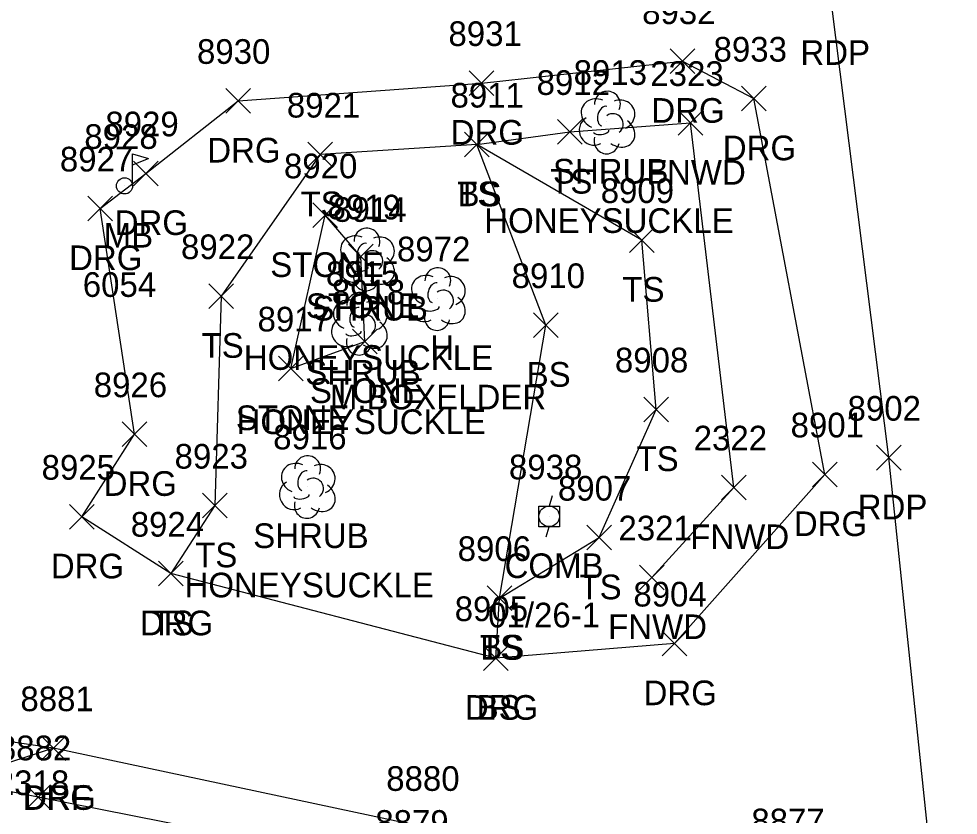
# Model space of a CAD drawing. Extents: x 1439173 to 1457902, y 641926 to 659889.
# Drawn here: x 1448240 to 1448316.2, y 646072.4 to 646137 of the extents above; entities that cross this region are included whole.
import ezdxf

# ---------------------------------------------------------------- set-up
doc = ezdxf.new("R2010")
doc.units = 0
for name, color, linetype in [('L_A', 7, 'Continuous'), ('L_C', 7, 'Continuous'), ('L_I', 7, 'Continuous'), ('L_TIC', 7, 'Continuous'), ('LASF', 7, 'Continuous'), ('LELB', 7, 'Continuous'), ('LFNC', 7, 'Continuous'), ('LMB', 7, 'Continuous'), ('LSH', 7, 'Continuous'), ('LTD', 7, 'Continuous'), ('P_A', 7, 'Continuous'), ('P_I', 7, 'Continuous'), ('P_TIC', 7, 'Continuous'), ('PET', 7, 'Continuous'), ('R_A', 7, 'Continuous'), ('R_I', 7, 'Continuous'), ('R_TIC', 7, 'Continuous'), ('RDF', 7, 'Continuous'), ('RDG', 7, 'Continuous'), ('U_A', 7, 'Continuous'), ('U_C', 7, 'Continuous'), ('U_I', 7, 'Continuous'), ('UP', 7, 'Continuous')]:
    doc.layers.add(name, color=color, linetype=linetype)

msp = doc.modelspace()

# ---------------------------------------------------------------- linework, layer by layer
at = {"layer": 'L_TIC'}
for points in [[(1448293.487, 646127.507), (1448295.487, 646129.507)], [(1448295.487, 646127.507), (1448293.487, 646129.507)], [(1448283.703, 646126.78), (1448285.703, 646128.78)], [(1448285.703, 646126.78), (1448283.703, 646128.78)], [(1448276.159, 646125.756), (1448278.159, 646127.756)], [(1448278.159, 646125.756), (1448276.159, 646127.756)], [(1448276.159, 646125.756), (1448278.159, 646127.756)], [(1448278.159, 646125.756), (1448276.159, 646127.756)], [(1448276.159, 646125.756), (1448278.159, 646127.756)], [(1448278.159, 646125.756), (1448276.159, 646127.756)], [(1448263.455, 646124.945), (1448265.455, 646126.945)], [(1448265.455, 646124.945), (1448263.455, 646126.945)], [(1448263.874, 646120.02), (1448265.874, 646122.02)], [(1448265.874, 646120.02), (1448263.874, 646122.02)], [(1448263.874, 646120.02), (1448265.874, 646122.02)], [(1448265.874, 646120.02), (1448263.874, 646122.02)], [(1448289.554, 646118.016), (1448291.554, 646120.016)], [(1448291.554, 646118.016), (1448289.554, 646120.016)], [(1448266.759, 646116.687), (1448268.759, 646118.687)], [(1448268.759, 646116.687), (1448266.759, 646118.687)], [(1448255.439, 646113.467), (1448257.439, 646115.467)], [(1448257.439, 646113.467), (1448255.439, 646115.467)], [(1448281.765, 646111.121), (1448283.765, 646113.121)], [(1448283.765, 646111.121), (1448281.765, 646113.121)], [(1448267.093, 646109.801), (1448269.093, 646111.801)], [(1448269.093, 646109.801), (1448267.093, 646111.801)], [(1448261.081, 646107.602), (1448263.081, 646109.602)], [(1448263.081, 646107.602), (1448261.081, 646109.602)], [(1448261.081, 646107.602), (1448263.081, 646109.602)], [(1448263.081, 646107.602), (1448261.081, 646109.602)], [(1448290.699, 646104.283), (1448292.699, 646106.283)], [(1448292.699, 646104.283), (1448290.699, 646106.283)], [(1448297.004, 646097.956), (1448299.004, 646099.956)], [(1448299.004, 646097.956), (1448297.004, 646099.956)], [(1448254.92, 646096.482), (1448256.92, 646098.482)], [(1448256.92, 646096.482), (1448254.92, 646098.482)], [(1448286.079, 646093.889), (1448288.079, 646095.889)], [(1448288.079, 646093.889), (1448286.079, 646095.889)], [(1448251.364, 646090.966), (1448253.364, 646092.966)], [(1448253.364, 646090.966), (1448251.364, 646092.966)], [(1448290.34, 646090.661), (1448292.34, 646092.661)], [(1448292.34, 646090.661), (1448290.34, 646092.661)], [(1448278.006, 646088.992), (1448280.006, 646090.992)], [(1448280.006, 646088.992), (1448278.006, 646090.992)], [(1448278.006, 646088.992), (1448280.006, 646090.992)], [(1448280.006, 646088.992), (1448278.006, 646090.992)], [(1448277.708, 646084.119), (1448279.708, 646086.119)], [(1448279.708, 646084.119), (1448277.708, 646086.119)], [(1448240.592, 646072.836), (1448242.592, 646074.836)], [(1448242.592, 646072.836), (1448240.592, 646074.836)]]:
    msp.add_lwpolyline(points, dxfattribs=at)
at = {"layer": 'LASF'}
for points in [[(1448262.081, 646108.602), (1448268.093, 646110.801), (1448267.759, 646117.687), (1448264.874, 646121.02)], [(1448262.081, 646108.602), (1448264.874, 646121.02)]]:
    msp.add_lwpolyline(points, dxfattribs=at)
at = {"layer": 'LELB'}
for points in [[(1448284.703, 646127.78), (1448294.487, 646128.507)], [(1448277.159, 646126.756), (1448284.703, 646127.78)], [(1448279.006, 646089.992), (1448287.079, 646094.889), (1448291.699, 646105.283), (1448290.554, 646119.016), (1448277.159, 646126.756), (1448264.455, 646125.945), (1448256.439, 646114.467), (1448255.92, 646097.482), (1448252.364, 646091.966)], [(1448278.708, 646085.119), (1448279.006, 646089.992), (1448282.765, 646112.121), (1448277.159, 646126.756)], [(1448337.946, 645782.103), (1448329.85, 645838.302), (1448325.495, 645886.125), (1448320.473, 645936.994), (1448317.454, 645969.991), (1448311.408, 646020.078), (1448307.55, 646061.606), (1448301.171, 646067.047), (1448272.2, 646067.792), (1448241.592, 646073.836), (1448234.771, 646075.206)]]:
    msp.add_lwpolyline(points, dxfattribs=at)
at = {"layer": 'LFNC'}
msp.add_lwpolyline([(1448291.34, 646091.661), (1448298.004, 646098.956), (1448294.487, 646128.507)], dxfattribs=at)
at = {"layer": 'LMB'}
for p, q in [((1448249.252, 646126.006), (1448250.546, 646125.624)), ((1448249.258, 646123.414), (1448249.257, 646126.008)), ((1448249.257, 646125.107), (1448250.539, 646125.615)), ((1448248.602, 646123.405), (1448248.602, 646123.405))]:
    msp.add_line(p, q, dxfattribs=at)
msp.add_circle((1448248.602, 646123.405), 0.656, dxfattribs=at)
at = {"layer": 'LSH'}
for p, q in [((1448287.706, 646128.593), (1448287.706, 646128.593)), ((1448287.706, 646128.593), (1448287.706, 646128.593)), ((1448268.207, 646117.489), (1448268.207, 646117.489)), ((1448268.207, 646117.489), (1448268.207, 646117.489)), ((1448267.625, 646112.282), (1448267.625, 646112.282)), ((1448267.625, 646112.282), (1448267.625, 646112.282)), ((1448263.403, 646099.044), (1448263.403, 646099.044)), ((1448263.403, 646099.044), (1448263.403, 646099.044))]:
    msp.add_line(p, q, dxfattribs=at)
for centre in [(1448287.753, 646130.027), (1448268.254, 646118.923), (1448267.672, 646113.716), (1448263.45, 646100.478)]:
    msp.add_arc(centre, 1.047, 335.52715, 180.95627, dxfattribs=at)
for centre, major_axis, ratio, start_param, end_param in [((1448286.914, 646129.26), (1.21, -0.512), 0.895232, 1.570796, 4.712389), ((1448287.498, 646129.052), (-0.208, -0.792), 0.645439, 3.141593, 6.283185), ((1448288.748, 646129.177), (-1.141, -0.483), 0.949671, 1.570796, 4.712389), ((1448288.206, 646128.427), (-0.5, 0.667), 0.989748, 3.141593, 6.283185), ((1448286.623, 646127.885), (0.584, -1.042), 0.959034, 3.141593, 6.283185), ((1448288.706, 646127.76), (-1.09, 0.792), 0.841452, 1.570796, 4.712389), ((1448287.248, 646127.843), (-0.625, -0.083), 0.423636, 0, 3.141593), ((1448287.706, 646127.093), (0.265, 1.061), 0.942809, 1.570796, 4.712389), ((1448267.415, 646118.155), (1.21, -0.512), 0.895232, 1.570796, 4.712389), ((1448269.249, 646118.072), (-1.141, -0.483), 0.949671, 1.570796, 4.712389), ((1448267.999, 646117.947), (-0.208, -0.792), 0.645439, 3.141593, 6.283185), ((1448267.124, 646116.78), (0.584, -1.042), 0.959034, 3.141593, 6.283185), ((1448268.707, 646117.322), (-0.5, 0.667), 0.989748, 3.141593, 6.283185), ((1448267.749, 646116.739), (-0.625, -0.083), 0.423636, 0, 3.141593), ((1448269.207, 646116.655), (-1.09, 0.792), 0.841452, 1.570796, 4.712389), ((1448268.208, 646115.989), (0.265, 1.061), 0.942809, 1.570796, 4.712389), ((1448266.834, 646112.948), (1.21, -0.512), 0.895232, 1.570796, 4.712389), ((1448268.667, 646112.865), (-1.141, -0.483), 0.949671, 1.570796, 4.712389), ((1448267.417, 646112.74), (-0.208, -0.792), 0.645439, 3.141593, 6.283185), ((1448268.125, 646112.115), (-0.5, 0.667), 0.989748, 3.141593, 6.283185), ((1448266.542, 646111.573), (0.584, -1.042), 0.959034, 3.141593, 6.283185), ((1448268.626, 646111.448), (-1.09, 0.792), 0.841452, 1.570796, 4.712389), ((1448267.167, 646111.531), (-0.625, -0.083), 0.423636, 0, 3.141593), ((1448267.626, 646110.782), (0.265, 1.061), 0.942809, 1.570796, 4.712389), ((1448262.612, 646099.711), (1.21, -0.512), 0.895232, 1.570796, 4.712389), ((1448264.445, 646099.628), (-1.141, -0.483), 0.949671, 1.570796, 4.712389), ((1448263.195, 646099.502), (-0.208, -0.792), 0.645439, 3.141593, 6.283185), ((1448262.32, 646098.336), (0.584, -1.042), 0.959034, 3.141593, 6.283185), ((1448263.903, 646098.878), (-0.5, 0.667), 0.989748, 3.141593, 6.283185), ((1448264.404, 646098.211), (-1.09, 0.792), 0.841452, 1.570796, 4.712389), ((1448263.404, 646097.544), (0.265, 1.061), 0.942809, 1.570796, 4.712389), ((1448262.945, 646098.294), (-0.625, -0.083), 0.423636, 0, 3.141593)]:
    msp.add_ellipse(centre, major_axis=major_axis, ratio=ratio, start_param=start_param, end_param=end_param, dxfattribs=at)
at = {"layer": 'LTD'}
msp.add_line((1448273.953, 646114.283), (1448273.953, 646114.283), dxfattribs=at)
msp.add_line((1448273.953, 646114.283), (1448273.953, 646114.283), dxfattribs=at)
msp.add_arc((1448274, 646115.717), 1.047, 335.52715, 180.95627, dxfattribs=at)
for centre, major_axis, ratio, start_param, end_param in [((1448273.162, 646114.95), (1.21, -0.512), 0.895232, 1.570796, 4.712389), ((1448274.995, 646114.867), (-1.141, -0.483), 0.949671, 1.570796, 4.712389), ((1448273.745, 646114.741), (-0.208, -0.792), 0.645439, 3.141593, 6.283185), ((1448272.87, 646113.575), (0.584, -1.042), 0.959034, 3.141593, 6.283185), ((1448274.453, 646114.117), (-0.5, 0.667), 0.989748, 3.141593, 6.283185), ((1448274.953, 646113.45), (-1.09, 0.792), 0.841452, 1.570796, 4.712389), ((1448273.954, 646112.783), (0.265, 1.061), 0.942809, 1.570796, 4.712389), ((1448273.495, 646113.533), (-0.625, -0.083), 0.423636, 0, 3.141593)]:
    msp.add_ellipse(centre, major_axis=major_axis, ratio=ratio, start_param=start_param, end_param=end_param, dxfattribs=at)
at = {"layer": 'P_TIC'}
for points in [[(1448309.559, 646100.37), (1448311.559, 646102.37)], [(1448311.559, 646100.37), (1448309.559, 646102.37)]]:
    msp.add_lwpolyline(points, dxfattribs=at)
at = {"layer": 'PET'}
msp.add_lwpolyline([(1448331.093, 645886.39), (1448326.626, 645936.531), (1448323.371, 645969.743), (1448318.606, 646019.753), (1448314.847, 646060.491), (1448310.559, 646101.37), (1448305.909, 646138.216), (1448301.567, 646183.522), (1448300.54, 646194.117), (1448294.771, 646239.411), (1448289.465, 646272.108), (1448284.567, 646306.828), (1448278.363, 646350.901), (1448273.976, 646377.726), (1448269.747, 646406.453), (1448262.128, 646452.793), (1448257.521, 646483.029), (1448252.725, 646509.609), (1448246.463, 646550.344), (1448240.194, 646586.206)], dxfattribs=at)
at = {"layer": 'R_TIC'}
for points in [[(1448292.826, 646132.521), (1448294.826, 646134.521)], [(1448294.826, 646132.521), (1448292.826, 646134.521)], [(1448276.556, 646130.745), (1448278.556, 646132.745)], [(1448278.556, 646130.745), (1448276.556, 646132.745)], [(1448256.824, 646129.299), (1448258.824, 646131.299)], [(1448258.824, 646129.299), (1448256.824, 646131.299)], [(1448298.617, 646129.48), (1448300.617, 646131.48)], [(1448300.617, 646129.48), (1448298.617, 646131.48)], [(1448298.617, 646129.48), (1448300.617, 646131.48)], [(1448300.617, 646129.48), (1448298.617, 646131.48)], [(1448249.316, 646123.422), (1448251.316, 646125.422)], [(1448251.316, 646123.422), (1448249.316, 646125.422)], [(1448245.62, 646120.573), (1448247.62, 646122.573)], [(1448247.62, 646120.573), (1448245.62, 646122.573)], [(1448248.421, 646102.273), (1448250.421, 646104.273)], [(1448250.421, 646102.273), (1448248.421, 646104.273)], [(1448304.375, 646099.014), (1448306.375, 646101.014)], [(1448306.375, 646099.014), (1448304.375, 646101.014)], [(1448304.375, 646099.014), (1448306.375, 646101.014)], [(1448306.375, 646099.014), (1448304.375, 646101.014)], [(1448244.138, 646095.583), (1448246.138, 646097.583)], [(1448246.138, 646095.583), (1448244.138, 646097.583)], [(1448251.364, 646090.966), (1448253.364, 646092.966)], [(1448253.364, 646090.966), (1448251.364, 646092.966)], [(1448292.195, 646085.302), (1448294.195, 646087.302)], [(1448294.195, 646085.302), (1448292.195, 646087.302)], [(1448277.708, 646084.119), (1448279.708, 646086.119)], [(1448279.708, 646084.119), (1448277.708, 646086.119)], [(1448241.851, 646076.817), (1448243.851, 646078.817)], [(1448243.851, 646076.817), (1448241.851, 646078.817)], [(1448241.851, 646076.817), (1448243.851, 646078.817)], [(1448243.851, 646076.817), (1448241.851, 646078.817)]]:
    msp.add_lwpolyline(points, dxfattribs=at)
at = {"layer": 'RDF'}
msp.add_lwpolyline([(1448242.851, 646077.817), (1448234.771, 646075.206), (1448217.67, 646066.325), (1448197.788, 646045.761), (1448178.618, 646020.996)], dxfattribs=at)
at = {"layer": 'RDG'}
for points in [[(1448305.375, 646100.014), (1448293.195, 646086.302), (1448278.708, 646085.119), (1448252.364, 646091.966), (1448245.138, 646096.583), (1448249.421, 646103.273), (1448246.62, 646121.573), (1448250.316, 646124.422), (1448257.824, 646130.299), (1448277.556, 646131.745), (1448293.826, 646133.521), (1448299.617, 646130.48)], [(1448305.375, 646100.014), (1448299.617, 646130.48)], [(1448314.847, 646060.491), (1448309.098, 646066.322), (1448302.677, 646067.913), (1448273.165, 646071.355), (1448242.851, 646077.817), (1448227.047, 646080.153), (1448212.156, 646077.85)]]:
    msp.add_lwpolyline(points, dxfattribs=at)
at = {"layer": 'UP'}
for p, q in [((1448283.279, 646098.275), (1448283.029, 646097.442)), ((1448282.196, 646095.775), (1448282.196, 646097.442)), ((1448282.196, 646097.442), (1448283.862, 646097.442)), ((1448283.862, 646097.442), (1448283.862, 646095.775)), ((1448283.029, 646096.609), (1448283.029, 646096.609)), ((1448283.862, 646095.775), (1448282.196, 646095.775)), ((1448282.779, 646094.942), (1448283.029, 646095.775))]:
    msp.add_line(p, q, dxfattribs=at)
msp.add_circle((1448283.029, 646096.609), 0.833, dxfattribs=at)

# ---------------------------------------------------------------- texts
at = {"layer": 'L_A'}
for s, p in [('SHRUB', (1448283.336, 646123.593)), ('FNWD', (1448290.951, 646123.507)), ('TS', (1448283.113, 646122.78)), ('TS', (1448275.568, 646121.756)), ('TS', (1448275.568, 646121.756)), ('BS', (1448275.6, 646121.756)), ('TS', (1448262.864, 646120.945)), ('MB', (1448246.909, 646118.405)), ('STONE', (1448260.417, 646116.02)), ('STONE', (1448260.417, 646116.02)), ('TS', (1448288.964, 646114.016)), ('STONE', (1448263.302, 646112.687)), ('SHRUB', (1448263.837, 646112.489)), ('TS', (1448254.848, 646109.467)), ('H', (1448273.386, 646109.283)), ('SHRUB', (1448263.255, 646107.282)), ('BS', (1448281.206, 646107.121)), ('STONE', (1448263.637, 646105.801)), ('STONE', (1448257.625, 646103.602)), ('STONE', (1448257.625, 646103.602)), ('TS', (1448290.108, 646100.283)), ('SHRUB', (1448259.033, 646094.044)), ('FNWD', (1448294.469, 646093.956)), ('TS', (1448254.329, 646092.482)), ('TS', (1448285.488, 646089.889)), ('TS', (1448250.774, 646086.966)), ('FNWD', (1448287.804, 646086.661)), ('TS', (1448277.416, 646084.992)), ('BS', (1448277.447, 646084.992)), ('BS', (1448277.149, 646080.119))]:
    msp.add_text(s, height=2, dxfattribs=at).set_placement(p)
at = {"layer": 'L_C'}
for s, p in [('HONEYSUCKLE', (1448277.769, 646119.593)), ('6054', (1448245.216, 646114.405)), ('HONEYSUCKLE', (1448258.27, 646108.489)), ('M.BOXELDER', (1448265.253, 646105.283)), ('HONEYSUCKLE', (1448257.688, 646103.282)), ('HONEYSUCKLE', (1448253.466, 646090.044))]:
    msp.add_text(s, height=2, dxfattribs=at).set_placement(p)
at = {"layer": 'L_I'}
for s, p in [('8913', (1448285.013, 646131.593)), ('2323', (1448291.227, 646131.507)), ('8912', (1448282.01, 646130.78)), ('8911', (1448275.033, 646129.756)), ('8911', (1448275.033, 646129.756)), ('8911', (1448275.033, 646129.756)), ('8921', (1448261.762, 646128.945)), ('8928', (1448245.342, 646126.405)), ('8920', (1448261.527, 646124.02)), ('8920', (1448261.527, 646124.02)), ('8909', (1448287.208, 646122.016)), ('8919', (1448265.058, 646120.687)), ('8914', (1448265.514, 646120.489)), ('8922', (1448253.179, 646117.467)), ('8972', (1448270.693, 646117.283)), ('8915', (1448264.932, 646115.282)), ('8910', (1448279.986, 646115.121)), ('8918', (1448265.401, 646113.801)), ('8917', (1448259.389, 646111.602)), ('8917', (1448259.389, 646111.602)), ('8908', (1448288.36, 646108.283)), ('8916', (1448260.655, 646102.044)), ('2322', (1448294.744, 646101.956)), ('8923', (1448252.66, 646100.482)), ('8907', (1448283.74, 646097.889)), ('8924', (1448249.105, 646094.966)), ('2321', (1448288.647, 646094.661)), ('8906', (1448275.612, 646092.992)), ('8906', (1448275.612, 646092.992)), ('8905', (1448275.369, 646088.119)), ('8882', (1448238.332, 646076.836)), ('2318', (1448238.167, 646074.011)), ('8879', (1448268.932, 646070.792))]:
    msp.add_text(s, height=2, dxfattribs=at).set_placement(p)
at = {"layer": 'P_A'}
for p in [(1448303.397, 646133.216), (1448308.047, 646096.37)]:
    msp.add_text('RDP', height=2, dxfattribs=at).set_placement(p)
at = {"layer": 'P_I'}
msp.add_text('8902', height=2, dxfattribs=at).set_placement((1448307.22, 646104.37))
at = {"layer": 'R_A'}
for s, p in [('DRG', (1448291.314, 646128.521)), ('DRG', (1448275.044, 646126.745)), ('DRG', (1448297.105, 646125.48)), ('DRG', (1448297.105, 646125.48)), ('DRG', (1448255.312, 646125.299)), ('DRG', (1448247.804, 646119.422)), ('DRG', (1448244.108, 646116.573)), ('DRG', (1448246.909, 646098.273)), ('DRG', (1448302.863, 646095.014)), ('DRG', (1448302.863, 646095.014)), ('DRG', (1448242.626, 646091.583)), ('DRG', (1448249.853, 646086.966)), ('DRG', (1448290.683, 646081.302)), ('DRG', (1448276.196, 646080.119)), ('DRG', (1448240.339, 646072.817)), ('DRF', (1448240.387, 646072.817))]:
    msp.add_text(s, height=2, dxfattribs=at).set_placement(p)
at = {"layer": 'R_I'}
for s, p in [('8932', (1448290.566, 646136.521)), ('8931', (1448274.863, 646134.745)), ('8930', (1448254.477, 646133.299)), ('8933', (1448296.357, 646133.48)), ('8933', (1448296.357, 646133.48)), ('8929', (1448247.048, 646127.422)), ('8927', (1448243.36, 646124.573)), ('8926', (1448246.106, 646106.273)), ('8901', (1448302.603, 646103.014)), ('8901', (1448302.603, 646103.014)), ('8925', (1448241.878, 646099.583)), ('8924', (1448249.105, 646094.966)), ('8904', (1448289.856, 646089.302)), ('8905', (1448275.369, 646088.119)), ('8881', (1448240.158, 646080.817)), ('8881', (1448240.158, 646080.817)), ('8880', (1448269.819, 646074.355)), ('8877', (1448299.417, 646070.913))]:
    msp.add_text(s, height=2, dxfattribs=at).set_placement(p)
at = {"layer": 'U_A'}
msp.add_text('COMB', height=2, dxfattribs=at).set_placement((1448279.415, 646091.609))
at = {"layer": 'U_C'}
msp.add_text('01/26-1', height=2, dxfattribs=at).set_placement((1448278.084, 646087.609))
at = {"layer": 'U_I'}
msp.add_text('8938', height=2, dxfattribs=at).set_placement((1448279.769, 646099.609))

doc.saveas('drawing.dxf')
